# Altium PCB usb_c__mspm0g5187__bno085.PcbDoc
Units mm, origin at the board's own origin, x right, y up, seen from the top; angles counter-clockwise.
Board outline 92 x 60 mm, 2 copper layers (Top, Bottom), stack 0 mm thick; 42 components, 34 nets, 214 pads, 80 vias.
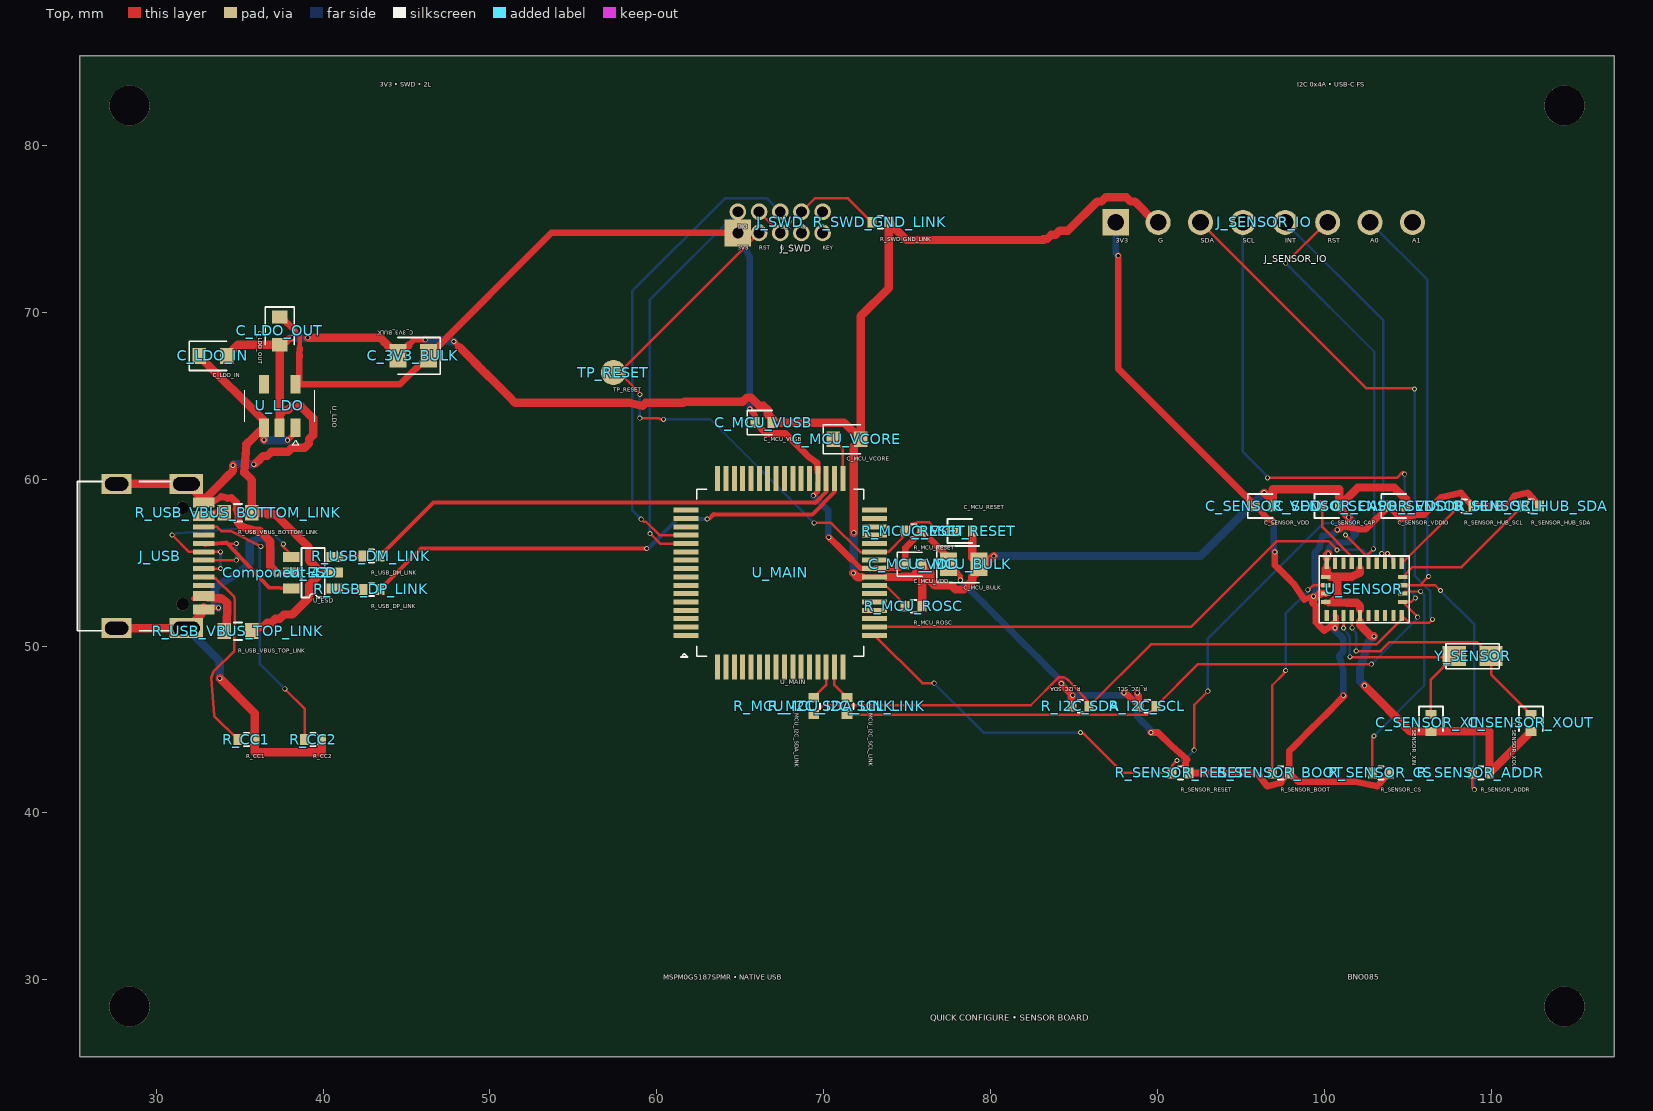
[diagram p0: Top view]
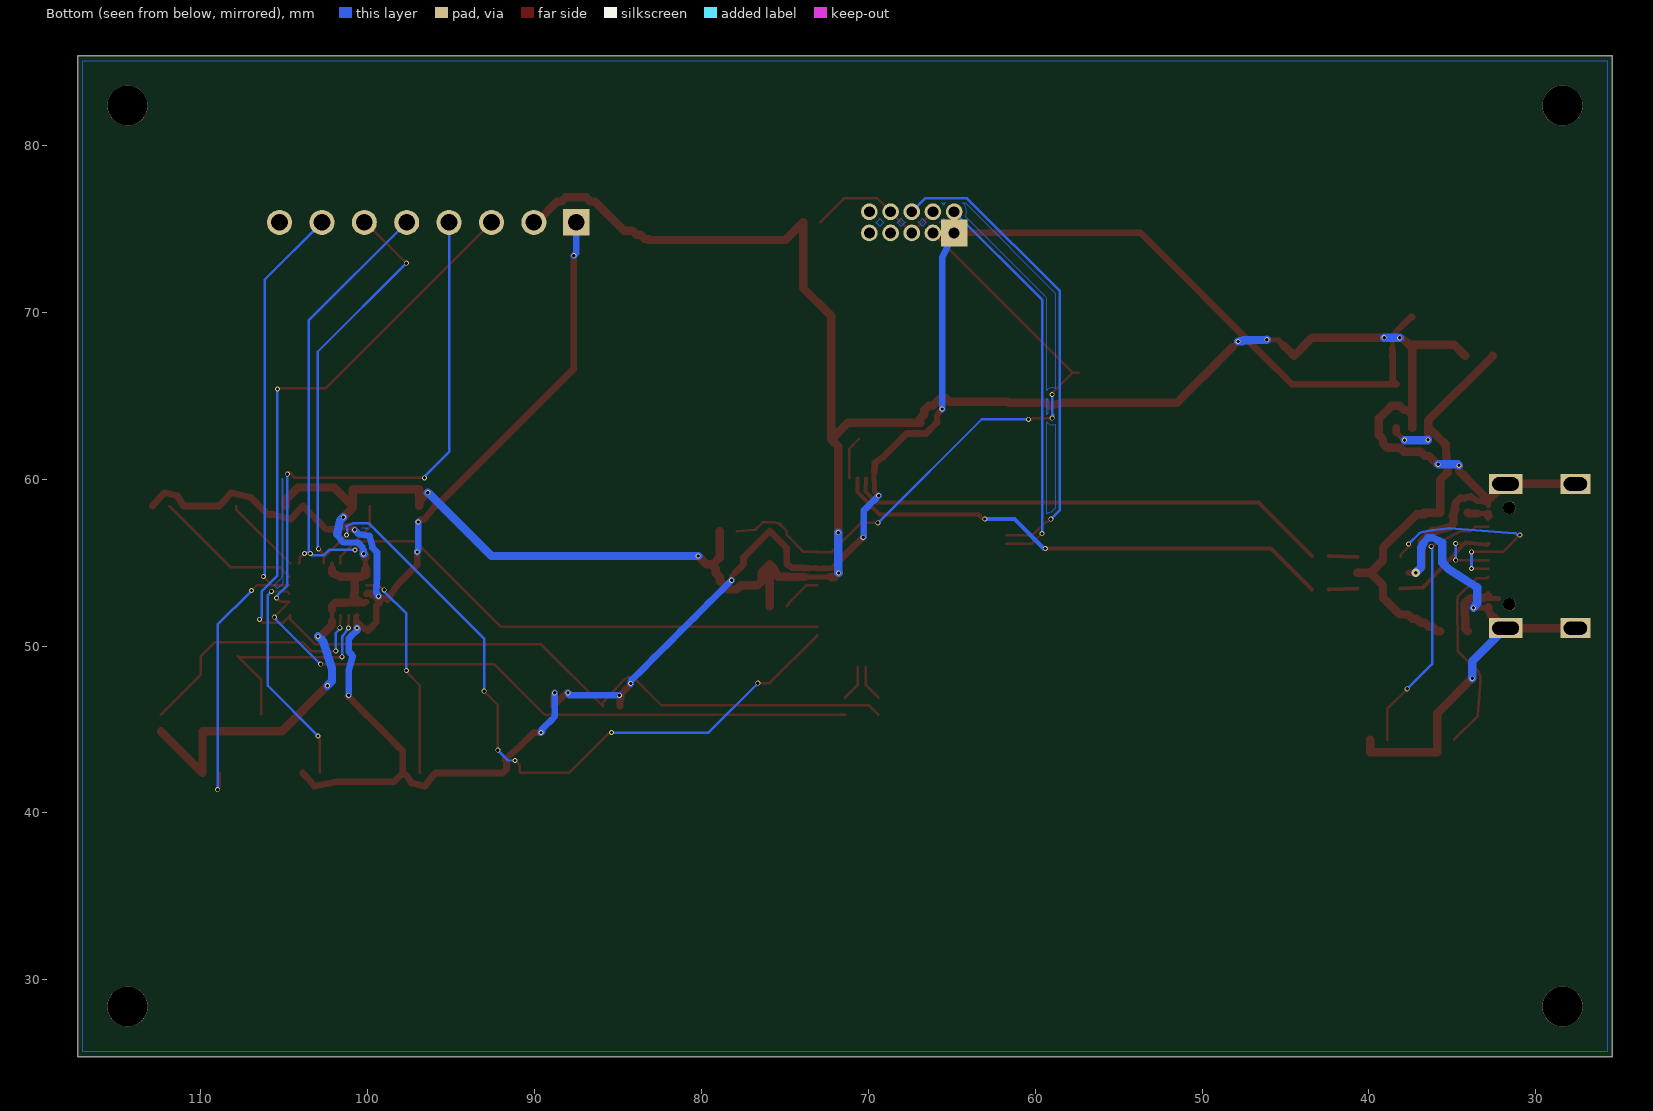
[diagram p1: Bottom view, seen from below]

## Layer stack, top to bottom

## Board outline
25.4,85.4 117.4,85.4 117.4,25.4 25.4,25.4

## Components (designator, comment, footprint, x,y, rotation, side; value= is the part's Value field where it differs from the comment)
C_3V3_BULK "" TSCIRCUIT-2.8500x1.4000mm 45.4,67.4 r180 top
C_LDO_IN "" TSCIRCUIT-2.4500x0.9500mm 33.4,67.4 r0 top
C_LDO_OUT "" TSCIRCUIT-0.9500x2.4500mm 37.4,68.9 r270 top
C_MCU_BULK "" TSCIRCUIT-2.8500x1.4000mm 78.4,54.9 r0 top
C_MCU_RESET "" TSCIRCUIT-1.5600x0.6400mm 78.4,56.9 r0 top
C_MCU_VCORE "" TSCIRCUIT-2.4500x0.9500mm 71.4,62.4 r0 top
C_MCU_VDD "" TSCIRCUIT-1.5600x0.6400mm 75.4,54.9 r0 top
C_MCU_VUSB "" TSCIRCUIT-1.5600x0.6400mm 66.4,63.4 r0 top
C_SENSOR_CAP "" TSCIRCUIT-1.5600x0.6400mm 100.4,58.4 r0 top
C_SENSOR_VDD "" TSCIRCUIT-1.5600x0.6400mm 96.4,58.4 r0 top
C_SENSOR_VDDIO "" TSCIRCUIT-1.5600x0.6400mm 104.4,58.4 r0 top
C_SENSOR_XIN "" TSCIRCUIT-0.6400x1.5600mm 106.4,45.4 r270 top
C_SENSOR_XOUT "" TSCIRCUIT-0.6400x1.5600mm 112.4,45.4 r270 top
Component-42 "" TSCIRCUIT-0.5000x0.5000mm 37.2,54.4 r0 top
J_SENSOR_IO "" TSCIRCUIT-19.2800x1.5000mm 96.4,75.4 r0 top
J_SWD "" TSCIRCUIT-6.0800x2.2700mm 67.4,75.4 r0 top
J_USB "" TSCIRCUIT-6.7732x9.8502mm 30.113,55.4 r90 top
R_CC1 "" TSCIRCUIT-1.5600x0.6400mm 35.4,44.4 r0 top
R_CC2 "" TSCIRCUIT-1.5600x0.6400mm 39.4,44.4 r0 top
R_I2C_SCL "" TSCIRCUIT-1.5600x0.6400mm 89.4,46.4 r180 top
R_I2C_SDA "" TSCIRCUIT-1.5600x0.6400mm 85.4,46.4 r180 top
R_MCU_I2C_SCL_LINK "" TSCIRCUIT-0.6400x1.5600mm 71.4,46.4 r270 top
R_MCU_I2C_SDA_LINK "" TSCIRCUIT-0.6400x1.5600mm 69.4,46.4 r270 top
R_MCU_RESET "" TSCIRCUIT-1.5600x0.6400mm 75.4,56.9 r0 top
R_MCU_ROSC "" TSCIRCUIT-1.5600x0.6400mm 75.4,52.4 r0 top
R_SENSOR_ADDR "" TSCIRCUIT-1.5600x0.6400mm 109.4,42.4 r0 top
R_SENSOR_BOOT "" TSCIRCUIT-1.5600x0.6400mm 97.4,42.4 r0 top
R_SENSOR_CS "" TSCIRCUIT-1.5600x0.6400mm 103.4,42.4 r0 top
R_SENSOR_HUB_SCL "" TSCIRCUIT-1.5600x0.6400mm 108.4,58.4 r0 top
R_SENSOR_HUB_SDA "" TSCIRCUIT-1.5600x0.6400mm 112.4,58.4 r0 top
R_SENSOR_RESET "" TSCIRCUIT-1.5600x0.6400mm 91.4,42.4 r0 top
R_SWD_GND_LINK "" TSCIRCUIT-1.5600x0.6400mm 73.4,75.4 r0 top
R_USB_DM_LINK "" TSCIRCUIT-1.5600x0.6400mm 42.9,55.4 r0 top
R_USB_DP_LINK "" TSCIRCUIT-1.5600x0.6400mm 42.9,53.4 r0 top
R_USB_VBUS_BOTTOM_LINK "" TSCIRCUIT-2.4500x0.9500mm 34.9,58 r0 top
R_USB_VBUS_TOP_LINK "" TSCIRCUIT-2.4500x0.9500mm 34.9,50.9 r0 top
TP_RESET "" TSCIRCUIT-1.5000x1.5000mm 57.4,66.4 r0 top
U_ESD "" TSCIRCUIT-3.6000x2.5000mm 39.4,54.4 r0 top
U_LDO "" TSCIRCUIT-2.5000x3.7000mm 37.4,64.4 r270 top
U_MAIN "" TSCIRCUIT-12.8000x12.8000mm 67.4,54.4 r0 top
U_SENSOR "" TSCIRCUIT-5.2000x3.8000mm 102.4,53.4 r0 top
Y_SENSOR "" TSCIRCUIT-3.6000x1.2000mm 108.9,49.4 r0 top

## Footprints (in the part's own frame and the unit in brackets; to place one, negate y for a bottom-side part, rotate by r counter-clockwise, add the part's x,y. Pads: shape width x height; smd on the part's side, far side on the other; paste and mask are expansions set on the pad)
TSCIRCUIT-0.5000x0.5000mm [mm]
TSCIRCUIT-0.6400x1.5600mm [mm]
  rect 0.54x0.64 smd: 1(-0.51,0) 2(0.51,0)
  silkscreen extent -0.98,-0.72 0.51,0.72
TSCIRCUIT-0.9500x2.4500mm [mm]
  rect 0.8x0.95 smd: 1(-0.825,0) 2(0.825,0)
  silkscreen extent -1.43,-0.87 0.82,0.88
TSCIRCUIT-1.5000x1.5000mm [mm]
  round 1.5 smd: 1(0,0)
TSCIRCUIT-1.5600x0.6400mm [mm]
  rect 0.54x0.64 smd: 1(-0.51,0) 2(0.51,0)
  silkscreen extent -0.98,-0.72 0.51,0.72
TSCIRCUIT-2.4500x0.9500mm [mm]
  rect 0.8x0.95 smd: 1(-0.825,0) 2(0.825,0)
  silkscreen extent -1.42,-0.87 0.82,0.87
TSCIRCUIT-2.5000x3.7000mm [mm]
  rect 1.1x0.6 smd: 1(1.3,0.95) 2(1.3,0) 3(1.3,-0.95) 4(-1.3,-0.95) 5(-1.3,0.95)
  silkscreen extent -0.95,-2.1 2.35,2.1
TSCIRCUIT-2.8500x1.4000mm [mm]
  rect 1.025x1.4 smd: 1(-0.913,0) 2(0.913,0)
  silkscreen extent -1.63,-1.1 0.91,1.1
TSCIRCUIT-3.6000x1.2000mm [mm]
  rect 1.4x1.2 smd: 1(-1.1,0) 2(1.1,0)
  silkscreen extent -1.6,-0.75 1.6,0.75
TSCIRCUIT-3.6000x2.5000mm [mm]
  rect 1x0.6 smd: 1(-1.3,-0.95) 2(-1.3,0) 3(-1.3,0.95) 4(1.3,0.95) 5(1.3,0) 6(1.3,-0.95)
  silkscreen extent -0.7,-1.49 0.7,1.49
TSCIRCUIT-5.2000x3.8000mm [mm]
  rect 0.25x0.675 smd: 1(-2.25,-1.562) 6(-2.25,1.563) 7(-1.75,1.563) 8(-1.25,1.563) 9(-0.75,1.563) 10(-0.25,1.563) 11(0.25,1.563) 12(0.75,1.563) 13(1.25,1.563) 14(1.75,1.563) 15(2.25,1.563) 20(2.25,-1.562) 21(1.75,-1.562) 22(1.25,-1.562) 23(0.75,-1.562) 24(0.25,-1.562) 25(-0.25,-1.562) 26(-0.75,-1.562) 27(-1.25,-1.562) 28(-1.75,-1.562)
  rect 0.575x0.25 smd: 2(-2.312,-0.75) 3(-2.312,-0.25) 4(-2.312,0.25) 5(-2.312,0.75) 16(2.312,0.75) 17(2.312,0.25) 18(2.312,-0.25) 19(2.312,-0.75)
  silkscreen extent -2.7,-2 2.7,2
TSCIRCUIT-6.0800x2.2700mm [mm]
  rect 1.6x1.6 hole 0.65: 1(-2.54,-0.635)
  round 1 hole 0.65: 2(-2.54,0.635) 3(-1.27,0.635) 4(0,0.635) 5(1.27,0.635) 6(2.54,0.635) 7(2.54,-0.635) 8(1.27,-0.635) 9(0,-0.635) 10(-1.27,-0.635)
TSCIRCUIT-6.7732x9.8502mm [mm]
  rect 0.3x1.3 smd: 1(-3.35,-2.737) 2(-3.05,-2.737) 3(-2.55,-2.737) 4(-2.25,-2.737) 5(-1.75,-2.737) 6(-1.25,-2.737) 7(-0.75,-2.737) 8(-0.25,-2.737) 9(0.25,-2.737) 10(0.75,-2.737) 11(1.25,-2.737) 12(1.75,-2.737) 13(2.55,-2.737) 14(2.25,-2.737) 15(3.35,-2.737) 16(3.05,-2.737)
  rect 1.2x2 hole 0.8 slot 1.6 at 90 deg: 17(-4.325,-1.693) 18(4.325,-1.693)
  rect 1.2x1.8 hole 0.8 slot 1.4 at 90 deg: 19(4.325,2.487) 20(-4.325,2.487)
  round 0.75 hole 0.75 unplated: NPTH-1(-2.9,-1.468) NPTH-2(2.9,-1.468)
  silkscreen extent -4.47,-0.75 4.47,4.83
TSCIRCUIT-12.8000x12.8000mm [mm]
  rect 1.5x0.3 smd: 1(-5.65,-3.75) 2(-5.65,-3.25) 3(-5.65,-2.75) 4(-5.65,-2.25) 5(-5.65,-1.75) 6(-5.65,-1.25) 7(-5.65,-0.75) 8(-5.65,-0.25) 9(-5.65,0.25) 10(-5.65,0.75) 11(-5.65,1.25) 12(-5.65,1.75) 13(-5.65,2.25) 14(-5.65,2.75) 15(-5.65,3.25) 16(-5.65,3.75) 33(5.65,3.75) 34(5.65,3.25) 35(5.65,2.75) 36(5.65,2.25) 37(5.65,1.75) 38(5.65,1.25) 39(5.65,0.75) 40(5.65,0.25) 41(5.65,-0.25) 42(5.65,-0.75) 43(5.65,-1.25) 44(5.65,-1.75) 45(5.65,-2.25) 46(5.65,-2.75) 47(5.65,-3.25) 48(5.65,-3.75)
  rect 0.3x1.5 smd: 17(-3.75,5.65) 18(-3.25,5.65) 19(-2.75,5.65) 20(-2.25,5.65) 21(-1.75,5.65) 22(-1.25,5.65) 23(-0.75,5.65) 24(-0.25,5.65) 25(0.25,5.65) 26(0.75,5.65) 27(1.25,5.65) 28(1.75,5.65) 29(2.25,5.65) 30(2.75,5.65) 31(3.25,5.65) 32(3.75,5.65) 49(3.75,-5.65) 50(3.25,-5.65) 51(2.75,-5.65) 52(2.25,-5.65) 53(1.75,-5.65) 54(1.25,-5.65) 55(0.75,-5.65) 56(0.25,-5.65) 57(-0.25,-5.65) 58(-0.75,-5.65) 59(-1.25,-5.65) 60(-1.75,-5.65) 61(-2.25,-5.65) 62(-2.75,-5.65) 63(-3.25,-5.65) 64(-3.75,-5.65)
  silkscreen extent -5.95,-5.05 5,5
TSCIRCUIT-19.2800x1.5000mm [mm]
  rect 1.6x1.6 hole 1: 1(-8.89,0)
  round 1.5 hole 1: 2(-6.35,0) 3(-3.81,0) 4(-1.27,0) 5(1.27,0) 6(3.81,0) 7(6.35,0) 8(8.89,0)

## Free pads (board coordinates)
  round 2.4 hole 2.4 unplated: NPTH-3(28.4,28.4) NPTH-4(114.4,28.4) NPTH-5(28.4,82.4) NPTH-6(114.4,82.4)

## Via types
v1: diameter 0.3, hole 0.2, Top to Bottom, 79 vias
v2: diameter 0.5, hole 0.2, Top to Bottom, 1 vias

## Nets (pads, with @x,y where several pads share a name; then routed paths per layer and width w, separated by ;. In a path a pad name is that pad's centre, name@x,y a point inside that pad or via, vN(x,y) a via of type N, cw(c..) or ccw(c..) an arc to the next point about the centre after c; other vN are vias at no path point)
".J_SWD > .pin2 to .U_MAIN > .pin12": J_SWD.2 U_MAIN.12 | length 23.9
  Top w0.15: v1(59.59,56.74) 59.688,56.646 59.705,56.646 60.201,56.15 U_MAIN.12
  Bottom w0.15: v1(59.59,56.74) 59.592,70.767 J_SWD.2
".J_SWD > .pin4 to .U_MAIN > .pin13": J_SWD.4 U_MAIN.13 | length 28.5
  Top w0.15: v1(59.06,57.616) 59.207,57.469 59.34,57.47 60.16,56.651 U_MAIN.13
  Bottom w0.15: v1(59.06,57.616) 58.521,58.155 58.521,71.279 64.083,76.841 66.594,76.841 J_SWD.4
".U_MAIN > .pin42 to .R_MCU_ROSC > .pin1": R_MCU_ROSC.1 U_MAIN.42 | length 2.4
  Top w0.15: U_MAIN.42 73.719,53.65 74.769,52.6 74.769,52.521 R_MCU_ROSC.1
".U_SENSOR > .CAP to .C_SENSOR_CAP > .pin1": C_SENSOR_CAP.1 U_SENSOR.9 | length 4.2
  Top w0.15: C_SENSOR_CAP.1 99.891,57.135 101.647,55.379 101.646,54.966 U_SENSOR.9
".U_SENSOR > .SENSOR_HUB_SCL to .R_SENSOR_HUB_SCL > .pin1": R_SENSOR_HUB_SCL.1 U_SENSOR.15 | length 4.8
  Top w0.15: U_SENSOR.15 107.89,58.202 R_SENSOR_HUB_SCL.1
".U_SENSOR > .SENSOR_HUB_SDA to .R_SENSOR_HUB_SDA > .pin1": R_SENSOR_HUB_SDA.1 U_SENSOR.16 | length 8.9
  Top w0.15: U_SENSOR.16 105.305,54.742 105.468,54.742 108.232,54.742 R_SENSOR_HUB_SDA.1
GND: C_3V3_BULK.2 C_LDO_IN.2 C_LDO_OUT.2 C_MCU_BULK.2 C_MCU_RESET.2 C_MCU_VCORE.2 C_MCU_VDD.2 C_MCU_VUSB.2 C_SENSOR_CAP.2 C_SENSOR_VDD.2 C_SENSOR_VDDIO.2 C_SENSOR_XIN.2 C_SENSOR_XOUT.2 J_SENSOR_IO.2 J_USB.1 J_USB.2 J_USB.15 J_USB.16 J_USB.17 J_USB.18 J_USB.19 J_USB.20 R_CC1.2 R_CC2.2 R_MCU_ROSC.2 R_SENSOR_ADDR.2 R_SWD_GND_LINK.2 U_ESD.2 U_LDO.2 U_MAIN.41 U_SENSOR.2 U_SENSOR.5 U_SENSOR.6 U_SENSOR.10 U_SENSOR.25 | length 223.9
  Top w0.25: U_SENSOR.2 U_SENSOR.2@100.375,52.639 ; U_SENSOR.5@100.088,54.275 U_SENSOR.5 U_SENSOR.5@100.375,54.15 ; U_SENSOR.6@100.088,54.625 100.088,54.9 U_SENSOR.6 ; U_SENSOR.6@100.15,54.625 U_SENSOR.6 ; U_SENSOR.6@100.15,55.3 U_SENSOR.6 ; 102.15,51.5 U_SENSOR.25 U_SENSOR.25@102.15,52.175 ; U_SENSOR.10@102.15,54.625 U_SENSOR.10
  Top w0.275: J_USB.16 J_USB.15@33.056,58.661
  Top w0.3: J_USB.1@32.699,51.9 J_USB.1 J_USB.1@32.849,52.2 ; J_USB.15@32.699,58.9 J_USB.15 ; J_USB.2 J_USB.2@32.899,52.3 ; J_USB.16@32.849,58.6 J_USB.15 ; J_USB.15@32.999,58.9 J_USB.15 ; 72.3,54.15 U_MAIN.41 73.144,54.15 73.237,54.15 73.331,54.15 73.425,54.15 73.519,54.15 73.612,54.15 73.706,54.15 U_MAIN.41@73.8,54.15
  Top w0.312: 45.418,68.331 45.675,68.35 45.931,68.369 v1(46.119,68.365)
  Top w0.325: J_USB.16 J_USB.16@32.849,58.6 ; J_USB.2@32.899,52.3 v1(33.731,52.3) ; v1(47.832,68.263) 48.166,67.929
  Top w0.35: v1(35.851,60.894) v1@35.859,60.947 ; 37.968,68.441 38.124,68.441 v1(38.153,68.477) ; 45.108,68.02 45.418,68.331
  Top w0.375: J_USB.15@33.056,58.661 33.504,58.707 33.9,58.963 ; v1@35.859,60.947 v1@35.959,60.947 ; U_SENSOR.2 U_SENSOR.2@100.275,52.587 ; U_SENSOR.2@100.375,52.639 100.509,52.634
  Top w0.4: 37.2,54.4 U_ESD.2@37.6,54.4 ; 72.175,54.12 72.205,54.15 ; U_SENSOR.2@100.275,52.587 100.556,52.775 100.837,52.963
  Top w0.425: C_LDO_OUT.2@37.785,68.258 37.968,68.441
  Top w0.437: 33.9,58.963 34.275,58.869 34.504,58.9 34.796,58.608
  Top w0.45: 72.205,54.15 72.3,54.15
  Top w0.475: 34.796,58.608 34.837,58.4 34.833,58.2 ; U_MAIN.41@73.8,54.15 74.253,54.15 74.707,54.15
  Top w0.5: J_USB.20 J_USB.17 31.874,51.075 32.474,51.675 32.699,51.9 ; J_USB.19 J_USB.18 31.874,59.725 32.474,59.125 32.699,58.9 ; J_USB.1@32.849,52.2 J_USB.2 ; 32.999,58.9 33.2,59.101 33.551,59.452 33.901,59.802 34.252,60.153 34.603,60.504 v1(34.603,60.841) ; v1(33.81,48.076) 35.91,45.976 R_CC1.2 35.91,43.65 39.91,43.65 R_CC2.2 ; C_LDO_IN.2 34.9,68.075 C_LDO_OUT.2 ; 34.833,58.2 34.967,57.8 34.9,57.4 35.15,57.15 35.923,56.926 36.186,56.926 36.838,56.275 36.838,54.762 37.2,54.4 ; v1@35.959,60.947 36.248,61.235 36.163,61.15 36.15,61.15 36.4,61.4 36.65,61.4 36.9,61.65 37.9,61.65 38.15,61.9 38.9,61.9 39.15,62.15 39.15,62.4 39.4,62.65 39.4,63.65 38.65,64.4 38.15,64.4 37.9,64.15 37.65,64.15 37.4,63.9 U_LDO.2 C_LDO_OUT.2 ; C_LDO_OUT.2@37.785,68.258 37.603,68.075 C_LDO_OUT.2 ; v1(39.081,68.491) 39.56,68.491 40.04,68.491 40.519,68.491 40.999,68.491 41.478,68.491 41.958,68.491 42.437,68.491 42.917,68.491 43.396,68.491 43.669,68.218 43.942,67.946 44.215,67.673 C_3V3_BULK.2 44.798,67.71 45.108,68.02 ; 48.166,67.929 48.5,67.595 48.834,67.261 49.169,66.926 49.503,66.592 49.837,66.258 50.171,65.924 50.505,65.59 50.84,65.255 51.174,64.921 51.508,64.587 51.997,64.587 52.485,64.587 52.973,64.587 53.462,64.587 53.95,64.587 54.439,64.587 54.927,64.587 55.415,64.587 55.904,64.587 56.392,64.587 56.881,64.587 57.369,64.587 57.857,64.587 58.346,64.587 59.15,64.4 59.323,64.587 59.811,64.587 60.3,64.587 60.788,64.587 61.276,64.587 61.587,64.587 61.65,64.65 65.15,64.65 65.4,64.9 65.65,64.9 66.15,64.4 66.4,64.4 66.65,64.15 66.65,63.9 66.9,63.65 66.9,63.4 C_MCU_VUSB.2 71.225,63.4 C_MCU_VCORE.2 ; v1(71.783,54.383) 72.043,54.113 72.175,54.12 ; 74.707,54.15 75.4,54.15 75.66,54.65 C_MCU_VDD.2 ; R_MCU_ROSC.2 C_MCU_VDD.2 ; C_MCU_RESET.2 78.91,55.303 C_MCU_BULK.2 ; v1(80.2,55.4) 80.137,55.337 80.132,55.337 79.913,55.118 79.695,54.9 C_MCU_BULK.2 ; J_SENSOR_IO.2 89.9,75.4 88.65,76.65 88.4,76.65 88.15,76.9 86.9,76.9 86.65,76.65 86.4,76.65 84.65,74.9 84.15,74.9 83.9,74.65 83.65,74.65 83.4,74.4 83.15,74.4 83.15,74.394 83.199,74.345 82.716,74.345 82.233,74.345 81.75,74.345 81.267,74.345 80.784,74.345 80.301,74.345 79.818,74.345 79.335,74.345 78.851,74.345 78.368,74.345 77.885,74.345 77.402,74.345 76.919,74.345 76.436,74.345 75.953,74.345 75.47,74.345 74.987,74.345 74.965,74.345 74.613,74.697 74.262,75.048 R_SWD_GND_LINK.2 73.91,71.464 72.225,69.779 72.225,69.287 72.225,68.795 72.225,68.303 72.225,67.812 72.225,67.32 72.225,66.828 72.225,66.336 72.225,65.844 72.225,65.352 72.225,64.86 72.225,64.368 72.225,63.876 72.225,63.384 72.225,62.892 C_MCU_VCORE.2 ; v1(96.4,59.2) 96.91,58.69 C_SENSOR_VDD.2 96.91,59.4 100.91,59.4 C_SENSOR_CAP.2 ; 100.088,54.275 100.088,54.625 ; 100.15,54.625 100.15,54.4 100.4,54.15 101.65,54.15 102.15,54.4 102.15,54.625 ; U_SENSOR.6@100.15,55.3 100.15,55.436 v1(100.249,55.535) ; U_SENSOR.5@100.375,54.15 100.775,54.15 100.775,53.338 100.837,52.963 ; 100.509,52.634 100.931,52.619 101.353,52.603 101.947,52.603 102.15,52.4 U_SENSOR.25@102.15,52.175 ; v1(101.469,57.73) 100.91,58.289 C_SENSOR_CAP.2 ; 102.15,51.5 102.15,51.275 102.275,51.15 102.834,50.591 v1(102.986,50.591) ; v1(102.417,47.634) 105.161,44.89 C_SENSOR_XIN.2 109.91,44.89 R_SENSOR_ADDR.2 110.087,42.577 C_SENSOR_XOUT.2 ; C_SENSOR_VDDIO.2 104.91,58.802 104.199,59.513 102.023,59.513 C_SENSOR_CAP.2 ; v1(71.813,56.799) v1(71.813,56.799) ; v1(71.813,56.799) 71.814,56.82 71.814,61.989 C_MCU_VCORE.2 ; C_MCU_VDD.2 75.91,54.89 76.4,54.4 76.4,53.9 76.65,53.65 77.65,53.65 77.9,53.4 78.4,53.4 78.9,53.9 78.9,54.15 79.15,54.4 79.15,54.65 79.4,54.9 C_MCU_BULK.2
  Bottom w0.375: 100.261,55.75 100.338,55.962 100.588,56.213 101.025,56.213 101.462,56.213 101.588,56.337 101.838,56.713
  Bottom w0.437: 36.181,56.494 36.473,56.494 36.748,56.143
  Bottom w0.45: 35.828,56.316 36.181,56.494 ; v1@100.261,55.548 100.261,55.75
  Bottom w0.475: 35.6,56.2 35.828,56.316
  Bottom w0.5: J_USB.17 33.81,49.071 v1(33.81,48.076) ; v1(33.731,52.3) 33.514,52.565 33.513,53.044 33.512,53.523 35.2,54.6 35.6,55 35.6,55.4 35.6,55.8 35.6,56.2 ; v1(34.603,60.841) 34.656,60.894 34.795,60.894 35.147,60.894 35.499,60.894 v1(35.851,60.894) ; 36.748,56.143 36.878,55.855 36.878,54.722 37.2,54.4 ; v1(38.153,68.477) 39.067,68.477 v1(39.081,68.491) ; v1(46.119,68.365) 46.593,68.354 47.067,68.344 47.541,68.333 47.595,68.278 47.771,68.278 v1(47.832,68.263) ; v1(71.783,54.383) 71.813,54.413 v1(71.813,56.799) ; v1(80.2,55.4) 80.683,55.4 81.166,55.4 81.649,55.4 82.132,55.4 82.615,55.4 83.099,55.4 83.582,55.4 84.065,55.4 84.548,55.4 85.031,55.4 85.514,55.4 85.997,55.4 86.48,55.4 86.963,55.4 87.446,55.4 87.93,55.4 88.413,55.4 92.6,55.4 v1(96.4,59.2) ; v1(100.249,55.535) v1@100.261,55.548 ; v1(101.469,57.73) 101.666,57.533 101.752,57.123 101.838,56.713 ; v1(102.417,47.634) 102.15,47.901 102.15,48.65 102.694,50.302 102.983,50.591 v1(102.986,50.591)
MAIN_RESET: C_MCU_RESET.1 J_SWD.10 R_MCU_RESET.1 TP_RESET.1 U_MAIN.38 | length 39.3
  Top w0.15: v1(58.981,63.66) 60.154,63.66 60.207,63.607 60.394,63.607 v1(60.402,63.599) ; v1(58.982,65.085) 59.023,65.126 57.75,66.4 TP_RESET.1 57.765,66.4 J_SWD.10 ; v1(69.428,57.392) 70.448,57.392 72.198,55.642 73.042,55.642 U_MAIN.38 73.889,55.65 74.889,56.651 R_MCU_RESET.1@74.889,56.899 ; R_MCU_RESET.1 75.256,57.266 75.34,57.266 75.256,57.35 75.65,57.423 75.9,57.425 76.15,57.425 76.323,57.425 76.764,56.984 C_MCU_RESET.1
  Bottom w0.15: v1(58.981,63.66) 58.931,63.71 58.931,63.858 58.982,63.909 v1(58.982,65.085) ; v1(60.402,63.599) 63.204,63.599 69.352,57.451 69.369,57.451 v1(69.428,57.392)
MCU_I2C_SCL_LOCAL: R_MCU_I2C_SCL_LINK.1 U_MAIN.50 | length 2.2
  Top w0.15: U_MAIN.50 70.65,47.66 R_MCU_I2C_SCL_LINK.1
MCU_I2C_SDA_LOCAL: R_MCU_I2C_SDA_LINK.1 U_MAIN.51 | length 2.2
  Top w0.15: R_MCU_I2C_SDA_LINK.1 70.15,47.66 U_MAIN.51
MSPM0_VCORE: C_MCU_VCORE.1 U_MAIN.32 | length 2.6
  Top w0.15: C_MCU_VCORE.1 71.15,61.825 U_MAIN.32
SENSOR_ADDR0: J_SENSOR_IO.7 R_SENSOR_ADDR.1 U_SENSOR.17 | length 40.7
  Top w0.15: v1(106.259,54.177) 105.732,53.65 U_SENSOR.17 106.657,53.65 v1(106.971,53.336) ; R_SENSOR_ADDR.1 108.89,41.517 108.973,41.434 108.973,41.427 v1(109,41.4)
  Bottom w0.15: J_SENSOR_IO.7 106.19,71.96 106.19,54.325 106.19,54.246 v1(106.259,54.177) ; v1(106.971,53.336) 107.034,53.273 107.034,53.255 109,51.289 v1(109,41.4)
SENSOR_ADDR1: J_SENSOR_IO.8
SENSOR_BOOT: R_SENSOR_BOOT.1 U_SENSOR.4 | length 13
  Top w0.15: R_SENSOR_BOOT.1 96.89,47.658 97.592,48.359 97.592,48.44 v1(97.695,48.543) ; v1(99.026,53.38) 99.335,53.65 U_SENSOR.4
  Bottom w0.15: v1(97.695,48.543) 97.695,51.954 99.027,53.285 99.027,53.341 v1(99.026,53.38)
SENSOR_CS: R_SENSOR_CS.1 U_SENSOR.18 | length 13.4
  Top w0.15: R_SENSOR_CS.1 102.89,44.524 102.979,44.613 v1(102.983,44.617) ; U_SENSOR.18 104.836,53.273 v1(105.787,53.284)
  Bottom w0.15: v1(102.983,44.617) 105.991,47.625 105.991,52.984 105.991,53.06 105.87,53.181 v1(105.787,53.284)
SENSOR_INT: J_SENSOR_IO.5 U_MAIN.47 U_SENSOR.14 | length 57.2
  Top w0.15: U_MAIN.47 92.017,51.15 97.167,56.3 100.25,56.3 100.698,55.852 v1(100.773,55.765) ; v1(103.446,55.55) 103.851,55.55 104.088,55.313 104.088,55.024 U_SENSOR.14 104.081,55.031 104.081,55.276 103.806,55.55 v1(103.8,55.55)
  Bottom w0.15: J_SENSOR_IO.5 103.554,69.516 103.554,55.658 v1(103.8,55.55) ; v1(100.773,55.765) 102.318,55.775 102.639,55.454 103.35,55.454 103.376,55.481 v1(103.446,55.55)
SENSOR_RESET: J_SENSOR_IO.6 R_SENSOR_RESET.1 U_MAIN.48 U_SENSOR.11 | length 68.3
  Top w0.15: U_MAIN.48 75.92,47.78 v1(76.624,47.78) ; v1(85.4,44.82) 85.485,44.735 85.607,44.735 87.942,42.4 R_SENSOR_RESET.1 90.89,42.856 91.092,43.058 v1(91.176,43.142) ; v1(92.213,43.762) 92.213,46.478 92.943,47.208 92.943,47.213 v1(93.031,47.301) ; v1(97.688,72.957) 97.712,72.981 100.131,75.4 J_SENSOR_IO.6 ; v1(101.276,56.665) 102.65,55.291 U_SENSOR.11 102.65,55.53 v1(102.952,55.832)
  Bottom w0.15: v1(76.624,47.78) 76.627,47.777 79.584,44.82 v1(85.4,44.82) ; v1(91.176,43.142) 91.617,43.166 92.204,43.753 v1(92.213,43.762) ; v1(93.031,47.301) 93.031,50.456 99.937,57.362 100.886,57.362 101.281,57.193 101.228,57.021 101.228,56.802 101.248,56.782 101.248,56.693 v1(101.276,56.665) ; v1(97.688,72.957) 103,67.645 103,55.909 103,55.88 v1(102.952,55.832)
SENSOR_SCL: J_SENSOR_IO.4 R_I2C_SCL.1 R_MCU_I2C_SCL_LINK.2 U_SENSOR.19 | length 70.8
  Top w0.15: R_MCU_I2C_SCL_LINK.2 89.4,45.89 R_I2C_SCL.1 92.421,48.911 102.62,48.911 102.811,48.911 v1(102.829,48.917) ; v1(96.602,60.084) 104.359,60.084 104.706,60.431 104.708,60.431 v1(104.826,60.313) ; v1(105.461,52.887) 105.222,52.65 U_SENSOR.19 105.609,51.754 v1(105.609,51.738)
  Bottom w0.15: J_SENSOR_IO.4 95.13,61.642 96.538,60.234 96.538,60.148 v1(96.602,60.084) ; v1(102.829,48.917) 105.489,51.576 105.489,51.618 v1(105.609,51.738) ; v1(104.826,60.313) 104.826,53.631 105.402,53.054 105.402,52.966 v1(105.461,52.887)
SENSOR_SDA: J_SENSOR_IO.3 R_I2C_SDA.1 R_MCU_I2C_SDA_LINK.2 U_SENSOR.20 | length 72.8
  Top w0.15: R_MCU_I2C_SDA_LINK.2 69.971,46.448 82.413,46.459 84.099,48.146 84.382,48.149 84.674,47.958 85.913,46.619 R_I2C_SDA.1 89.612,50.102 103.128,50.1 104.662,51.615 U_SENSOR.20 105.079,51.408 105.079,51.396 106.283,51.396 v1(106.49,51.603) ; J_SENSOR_IO.3 102.519,65.471 105.342,65.471 105.362,65.471 v1(105.417,65.416)
  Bottom w0.15: v1(105.417,65.416) 105.417,54.234 106.347,53.304 106.347,51.746 v1(106.49,51.603)
SENSOR_XIN: C_SENSOR_XIN.1 U_SENSOR.27 Y_SENSOR.1 | length 13
  Top w0.15: U_SENSOR.27 U_SENSOR.27 v1(101.16,51.085) ; v1(101.544,49.355) 101.551,49.324 101.582,49.324 107.724,49.324 Y_SENSOR.1 106.4,48 C_SENSOR_XIN.1
  Bottom w0.15: v1(101.16,51.085) 101.153,51.085 101.52,50.583 v1(101.544,49.355)
SENSOR_XOUT: C_SENSOR_XOUT.1 U_SENSOR.26 Y_SENSOR.2 | length 15.4
  Top w0.15: U_SENSOR.26 101.613,51.8 v1(101.675,51.1) ; v1(101.921,49.712) 101.926,49.707 102.138,49.707 103.38,49.707 103.915,50.241 109.159,50.241 Y_SENSOR.2 110,48.31 C_SENSOR_XOUT.1
  Bottom w0.15: v1(101.675,51.1) 101.621,51.09 101.621,51.084 101.921,50.785 v1(101.921,49.712)
swd-ground-1-to-2: J_SWD.3 J_SWD.5 J_SWD.9 R_SWD_GND_LINK.1 | length 8.8
  Top w0.15: J_SWD.3 J_SWD.9 J_SWD.5 69.481,76.846 71.471,76.846 71.471,76.819 R_SWD_GND_LINK.1
usb-dm-device: R_USB_DM_LINK.1 U_ESD.4 | length 1.7
  Top w0.25: U_ESD.4 R_USB_DM_LINK.1
usb-dm-mcu: R_USB_DM_LINK.2 U_MAIN.30 | length 29.2
  Top w0.25: R_USB_DM_LINK.2 46.621,58.611 69.501,58.593 70.166,59.262 U_MAIN.30
usb-dm-port-tie: J_USB.7 J_USB.9 U_ESD.3 | length 13.4
  Top w0.15: v1(30.956,56.662) 31.968,55.65 J_USB.9 v1(33.85,55.65) ; J_USB.7 v1(33.85,54.65) ; v1(37.617,56.127) 37.533,56.043 38.1,55.477 U_ESD.3
  Bottom w0.15: v1(30.956,56.662) 31.091,56.662 31.197,56.768 31.296,56.768 35.189,57.075 36.209,56.953 36.72,56.871 36.976,56.769 v1(37.617,56.127) ; v1(33.85,54.65) v1(33.85,55.65)
usb-dp-device: R_USB_DP_LINK.1 U_ESD.6 | length 1.7
  Top w0.25: U_ESD.6 R_USB_DP_LINK.1
usb-dp-mcu: R_USB_DP_LINK.2 U_MAIN.31 | length 30.5
  Top w0.25: R_USB_DP_LINK.2 45.859,55.849 v1(59.393,55.849) ; v1(63.019,57.62) 63.056,57.657 63.164,57.657 63.411,57.904 69.321,57.894 70.656,59.237 U_MAIN.31
  Bottom w0.25: v1(59.393,55.849) 59.411,55.867 59.497,55.867 61.25,57.62 v1(63.019,57.62)
usb-dp-port-tie: J_USB.8 J_USB.10 U_ESD.1 | length 11.4
  Top w0.15: J_USB.8 v1(34.8,55.15) ; J_USB.10 v1(34.8,56.15)
  Top w0.25: J_USB.10 32.925,56.074 34.203,56.209 36.754,53.512 U_ESD.1
  Bottom w0.15: v1(34.8,55.15) v1(34.8,56.15)
USB_CC1: J_USB.6 R_CC1.1 | length 12
  Top w0.15: J_USB.6 32.937,54.062 33.561,54.062 34.682,52.941 34.691,52.777 34.683,49.717 33.456,48.501 33.302,48.102 33.464,45.824 R_CC1.1
USB_CC2: J_USB.12 R_CC2.1 | length 16.5
  Top w0.15: J_USB.12 33.649,57.15 33.904,56.895 34.49,56.895 v1(36.271,55.983) ; v1(37.706,47.439) 37.727,47.418 38.89,46.255 R_CC2.1
  Bottom w0.15: v1(36.271,55.983) 36.217,55.929 36.217,55.821 36.217,48.928 v1(37.706,47.439)
USB_VBUS_BOTTOM_LOCAL: J_USB.13 J_USB.14 R_USB_VBUS_BOTTOM_LINK.1 | length 1.5
  Top w0.3: J_USB.14 J_USB.14@32.849,57.8 ; J_USB.13 32.927,57.95 33.005,57.95 33.083,57.95 33.161,57.95 33.239,57.95 33.317,57.95 33.394,57.95 33.472,57.95 33.499,57.95
  Top w0.475: J_USB.13@32.849,57.8 J_USB.13 ; 33.499,57.95 R_USB_VBUS_BOTTOM_LINK.1@33.762,57.95
  Top w0.5: R_USB_VBUS_BOTTOM_LINK.1@33.762,57.95 34.025,57.95 R_USB_VBUS_BOTTOM_LINK.1
USB_VBUS_TOP_LOCAL: J_USB.3 J_USB.4 R_USB_VBUS_TOP_LINK.1 | length 6.6
  Top w0.3: J_USB.4 32.849,53 J_USB.3 32.834,52.865 32.24,52.865 32.646,52.865 33.052,52.865 33.458,52.865 33.499,52.865 ; J_USB.3@33.125,52.904 33.224,52.85 J_USB.3@33.349,52.85
  Top w0.423: J_USB.3@32.999,52.948 33.432,52.907 33.864,52.865
  Top w0.442: J_USB.3@33.349,52.85 33.4,52.9 33.499,52.889
  Top w0.5: J_USB.3@32.999,52.948 J_USB.3@33.125,52.904 ; 33.499,52.865 33.864,52.865 ; 33.499,52.889 33.849,52.85 33.958,52.85 34.25,52.591 34.227,51.042 R_USB_VBUS_TOP_LINK.1
VBUS5: C_LDO_IN.1 R_USB_VBUS_BOTTOM_LINK.2 R_USB_VBUS_TOP_LINK.2 U_ESD.5 U_LDO.1 U_LDO.3 | length 28.7
  Top w0.325: v1(37.864,62.342) 38.022,62.486 U_LDO.1@38.35,62.814
  Top w0.45: U_LDO.1@38.35,62.814 U_LDO.1
  Top w0.5: C_LDO_IN.1 36.45,63.525 U_LDO.3 ; R_USB_VBUS_TOP_LINK.2 35.9,50.9 36.15,51.15 36.4,51.15 36.65,51.4 36.9,51.4 37.15,51.65 37.4,51.65 37.65,51.9 38.15,51.9 39.15,52.9 39.15,53.65 39.9,54.4 ; v1(36.454,62.363) 36.454,62.73 36.454,63.096 U_LDO.3 ; U_LDO.3 36.101,62.766 35.752,62.433 35.404,62.099 35.275,60.4 35.725,59.95 R_USB_VBUS_BOTTOM_LINK.2 36.225,58 36.725,58 36.65,57.925 36.65,57.9 37.15,57.9 39.15,55.9 39.15,55.15 39.9,54.4 ; 39.9,54.4 U_ESD.5 39.9,54.4
  Bottom w0.5: v1(36.454,62.363) 36.475,62.342 v1(37.864,62.342)
VCC_3V3: C_3V3_BULK.1 C_LDO_OUT.1 C_MCU_BULK.1 C_MCU_VDD.1 C_MCU_VUSB.1 C_SENSOR_VDD.1 C_SENSOR_VDDIO.1 J_SENSOR_IO.1 J_SWD.1 R_I2C_SCL.2 R_I2C_SDA.2 R_MCU_RESET.2 R_SENSOR_BOOT.2 R_SENSOR_CS.2 R_SENSOR_HUB_SCL.2 R_SENSOR_HUB_SDA.2 R_SENSOR_RESET.2 U_LDO.5 U_MAIN.29 U_MAIN.40 U_SENSOR.3 U_SENSOR.28 | length 168.5
  Top w0.25: U_SENSOR.3@99.8,53.087 U_SENSOR.3 U_SENSOR.3@99.8,53.187 ; 100.6,51.4 100.65,51.589 U_SENSOR.28
  Top w0.275: 38.309,68.903 38.594,68.628 38.59,68.241 38.587,67.854
  Top w0.3: v1(69.378,59.022) 69.494,59.121 69.5,59.128 69.642,59.272 69.646,59.661 U_MAIN.29 U_MAIN.29@69.65,60.425 ; 71.668,55.202 71.939,54.938 72.21,54.673 ; U_MAIN.40@72.77,54.658 U_MAIN.40
  Top w0.312: 72.21,54.673 U_MAIN.40@72.49,54.666 ; C_MCU_BULK.1@77.962,54.426 78.199,54.188 v1(78.196,53.95)
  Top w0.319: U_SENSOR.28 100.717,51.77 100.689,51.5
  Top w0.327: U_MAIN.40@73.162,54.705 73.26,54.677 U_MAIN.40@73.583,54.683
  Top w0.337: U_MAIN.40@72.49,54.666 U_MAIN.40@72.77,54.658 ; U_MAIN.40 U_MAIN.40@73.162,54.705
  Top w0.35: 38.025,69.178 38.309,68.903 ; v1(65.58,64.219) 65.735,64.026 65.89,63.833 65.89,63.617 C_MCU_VUSB.1
  Top w0.387: 38.583,67.467 38.587,67.854 ; U_MAIN.40@73.583,54.683 73.905,54.689
  Top w0.4: C_LDO_OUT.1 37.456,69.728 37.74,69.453 38.025,69.178 ; 38.583,67.467 38.58,67.08 38.576,66.693 38.572,66.306 38.569,65.919 U_LDO.5 44.613,65.7 C_3V3_BULK.1 53.672,74.771 J_SWD.1 ; C_MCU_VUSB.1 66.109,63.181 66.327,62.963 66.546,62.744 66.932,62.744 67.319,62.744 67.706,62.744 67.983,62.467 68.261,62.189 68.539,61.911 68.817,61.633 69.094,61.356 69.6,61 U_MAIN.29@69.65,60.425 ; v1(70.313,56.524) 70.584,56.26 70.855,55.995 71.126,55.731 71.397,55.467 71.668,55.202 ; 73.905,54.689 74.228,54.694 74.55,54.7 C_MCU_VDD.1 74.89,55.88 R_MCU_RESET.2 77.488,55.323 C_MCU_BULK.1 77.725,54.663 C_MCU_BULK.1@77.962,54.426 ; v1(84.246,47.759) 84.3,47.705 84.3,47.655 84.497,47.459 84.693,47.262 84.89,47.065 84.89,46.733 R_I2C_SDA.2 84.89,46.809 84.826,46.873 84.826,46.96 v1(84.923,47.057) ; v1(87.649,73.403) 87.649,66.641 C_SENSOR_VDD.1 95.975,58.4 96.6,57.6 96.799,57.576 96.842,57.576 v1(96.979,57.439) ; v1(88,47.2) 88.09,47.2 R_I2C_SCL.2 88.89,46.711 88.89,47.023 88.8,47.113 v1(88.8,47.2) ; v1(89.62,44.82) 89.828,44.822 90.036,44.823 90.314,44.551 90.592,44.279 90.87,44.006 91.8,43.2 91.704,43.189 91.694,42.907 91.684,42.626 R_SENSOR_RESET.2 92.278,42.4 92.646,42.4 93.014,42.4 93.382,42.4 93.75,42.4 94.118,42.4 94.486,42.4 94.854,42.4 95.222,42.4 95.59,42.4 95.958,42.4 96.121,42.228 96.6,41.6 97.4,41.8 97.655,42.24 R_SENSOR_BOOT.2 ; v1(97.042,55.64) 97.042,55.255 97.042,54.869 97.316,54.595 97.59,54.321 97.864,54.047 98.139,53.773 98.8,52.8 100,53.2 U_SENSOR.3 ; v1(99.362,52.99) 99.8,53.087 ; 99.8,53.187 99.7,53.2 99.3,52.6 99.503,52.422 99.503,52.094 99.503,51.765 99.503,51.437 99.752,51.188 100,50.939 100.4,51.2 100.6,51.4 ; v1(100.645,51.088) 100.681,51.429 100.689,51.5 ; v1(100.786,56.968) 100.829,57.011 100.966,57.011 101.1,57.2 102.117,57.011 102.501,57.011 102.779,57.289 103.056,57.566 103.334,57.844 103.612,58.122 C_SENSOR_VDDIO.1 104.138,58.144 104.6,57.6 105.677,57.892 105.999,57.893 106.256,58.152 106.512,58.412 106.768,58.671 107.025,58.93 108.2,59.2 108.645,58.665 R_SENSOR_HUB_SCL.2 109.265,58.4 109.62,58.4 109.975,58.4 110.33,58.4 110.685,58.4 111.04,58.4 111.4,59 112.2,59.2 R_SENSOR_HUB_SDA.2 ; v1(101.147,47.05) 101.199,47.006 100.925,46.732 100.651,46.458 100.377,46.184 100.102,45.91 99.828,45.636 99.554,45.362 99.28,45.088 99.006,44.814 98.732,44.54 98.458,44.266 98.184,43.992 97.91,43.717 97.91,43.388 97.91,43.059 97.91,42.729 R_SENSOR_BOOT.2 ; R_SENSOR_CS.2 103.645,42.135 103.2,41.6 101.86,41.87 101.48,41.87 101.1,41.87 100.72,41.87 100.34,41.87 99.96,41.87 99.58,41.87 99.2,41.87 98.82,41.87 98.44,41.87 98.175,42.135 R_SENSOR_BOOT.2
  Bottom w0.4: J_SWD.1 65.58,73.259 65.58,72.866 65.58,72.473 65.58,72.08 65.58,71.687 65.58,71.294 65.58,70.901 65.58,70.508 65.58,70.115 65.58,69.722 65.58,69.329 65.58,68.935 65.58,68.542 65.58,68.149 65.58,67.756 65.58,67.363 65.58,66.97 65.58,66.577 65.58,66.184 65.58,65.791 65.58,65.398 65.58,65.005 65.58,64.612 v1(65.58,64.219) ; v1(69.378,59.022) 69.604,58.796 69.83,58.57 70.056,58.344 70.281,58.119 70.281,57.743 70.281,57.368 70.281,56.993 70.281,56.617 70.281,56.556 v1(70.313,56.524) ; v1(78.196,53.95) 78.201,53.952 78.475,53.677 78.75,53.402 79.025,53.127 79.3,52.852 79.575,52.578 79.849,52.303 80.124,52.028 80.399,51.753 80.674,51.478 80.949,51.204 81.223,50.929 81.498,50.654 81.773,50.379 82.048,50.105 82.322,49.83 82.597,49.555 82.872,49.28 83.147,49.005 83.422,48.731 83.696,48.456 83.971,48.181 84.246,47.906 v1(84.246,47.759) ; v1(84.923,47.057) 87.928,47.062 87.928,47.128 v1(88,47.2) ; J_SENSOR_IO.1 87.51,73.547 87.614,73.443 87.614,73.438 v1(87.649,73.403) ; v1(88.8,47.2) 88.8,46.843 88.8,46.486 88.8,46.128 88.8,45.771 89.052,45.519 89.304,45.267 89.557,45.014 89.557,44.883 v1(89.62,44.82) ; v1(96.979,57.439) 96.979,57.102 96.979,56.764 96.979,56.427 96.979,56.089 96.979,55.752 97.023,55.708 97.023,55.659 v1(97.042,55.64) ; v1(99.362,52.99) 99.45,53.118 99.45,53.151 99.5,53.2 99.45,54.215 99.45,54.569 99.45,54.923 99.45,55.278 99.45,55.632 99.717,55.899 99.9,56.6 100.519,56.701 v1(100.786,56.968) ; v1(100.645,51.088) 100.6,51 100.936,50.665 101.139,50.454 101.14,50.076 101.141,49.698 100.9,49.4 101.143,48.563 101.144,48.185 101.145,47.806 101.146,47.428 v1(101.147,47.05)
pads on no net: J_SWD.6 J_SWD.7 J_SWD.8 J_USB.5 J_USB.11 J_USB.NPTH-1 J_USB.NPTH-2 U_LDO.4 U_MAIN.1 U_MAIN.2 U_MAIN.3 U_MAIN.4 U_MAIN.5 U_MAIN.6 U_MAIN.7 U_MAIN.8 U_MAIN.9 U_MAIN.10 U_MAIN.11 U_MAIN.14 U_MAIN.15 U_MAIN.16 U_MAIN.17 U_MAIN.18 U_MAIN.19 U_MAIN.20 U_MAIN.21 U_MAIN.22 U_MAIN.23 U_MAIN.24 U_MAIN.25 U_MAIN.26 U_MAIN.27 U_MAIN.28 U_MAIN.33 U_MAIN.34 U_MAIN.35 U_MAIN.36 U_MAIN.37 U_MAIN.39 U_MAIN.43 U_MAIN.44 U_MAIN.45 U_MAIN.46 U_MAIN.49 U_MAIN.52 U_MAIN.53 U_MAIN.54 U_MAIN.55 U_MAIN.56 U_MAIN.57 U_MAIN.58 U_MAIN.59 U_MAIN.60 U_MAIN.61 U_MAIN.62 U_MAIN.63 U_MAIN.64 U_SENSOR.1 U_SENSOR.7 U_SENSOR.8 U_SENSOR.12 U_SENSOR.13 U_SENSOR.21 U_SENSOR.22 U_SENSOR.23 U_SENSOR.24
copper on no net:
  other v2: 37.2,54.4

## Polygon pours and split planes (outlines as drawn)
GND on Bottom (solid): 117.1,85.1 25.7,85.1 25.7,25.7 117.1,25.7
GND on Bottom (solid): 65.601,76.566 65.389,76.566 65.39,76.565 65.484,76.452 65.495,76.43 65.506,76.452 65.6,76.565
GND on Bottom (solid): 65.495,75.64 65.484,75.618 65.399,75.515 65.591,75.515 65.506,75.618
GND on Bottom (solid): 65.61,75.496 65.61,75.304 65.713,75.389 65.735,75.4 65.713,75.411
GND on Bottom (solid): 69.305,75.64 69.294,75.618 69.2,75.505 69.087,75.411 69.065,75.4 69.087,75.389 69.2,75.295 69.294,75.182 69.305,75.16 69.316,75.182 69.41,75.295 69.523,75.389 69.545,75.4 69.523,75.411 69.41,75.505 69.316,75.618
GND on Bottom (solid): 68.035,75.64 68.024,75.618 67.93,75.505 67.817,75.411 67.795,75.4 67.817,75.389 67.93,75.295 68.024,75.182 68.035,75.16 68.046,75.182 68.14,75.295 68.253,75.389 68.275,75.4 68.253,75.411 68.14,75.505 68.046,75.618
GND on Bottom (solid): 66.765,75.64 66.754,75.618 66.66,75.505 66.547,75.411 66.525,75.4 66.547,75.389 66.66,75.295 66.754,75.182 66.765,75.16 66.776,75.182 66.87,75.295 66.983,75.389 67.005,75.4 66.983,75.411 66.87,75.505 66.776,75.618
GND on Bottom (solid): 64.331,76.566 64.197,76.566 58.796,71.165 58.796,65.437 58.829,65.455 58.904,65.477 58.982,65.485 59.06,65.477 59.135,65.455 59.204,65.418 59.265,65.368 59.315,65.307 59.316,65.304 59.317,70.767 59.322,70.821 59.338,70.872 59.363,70.92 59.398,70.961 64.173,75.737 64.167,75.748 64.124,75.889 64.11,76.035 64.124,76.181 64.167,76.322 64.236,76.452 64.33,76.565
GND on Bottom (solid): 59.316,64.866 59.315,64.863 59.265,64.802 59.257,64.796 59.257,63.948 59.264,63.943 59.314,63.882 59.316,63.878
GND on Bottom (solid): 59.316,63.442 59.314,63.438 59.264,63.377 59.203,63.327 59.134,63.29 59.059,63.268 58.981,63.26 58.903,63.268 58.828,63.29 58.796,63.307 58.796,58.269 59.05,58.015 59.06,58.016 59.138,58.008 59.213,57.986 59.282,57.949 59.315,57.921
GND on Bottom (solid): 100.339,57.087 100.051,57.087 99.982,57.019 100.327,57.075
GND on Bottom (solid): 105.142,60.071 105.109,60.03 105.101,60.024 105.101,53.745 105.416,53.43 105.418,53.438 105.455,53.507 105.505,53.567 105.565,53.617 105.617,53.645 105.223,54.04 105.188,54.081 105.163,54.129 105.147,54.18 105.142,54.234

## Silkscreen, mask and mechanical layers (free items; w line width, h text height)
Top Overlay:
  text "3V3 • SWD • 2L" at 43.4,83.4 h0.48
  text "I2C 0x4A • USB-C FS" at 98.4,83.4 h0.5
  text "MSPM0G5187SPMR • NATIVE USB" at 60.4,29.9 h0.52
  text "BNO085" at 101.4,29.9 h0.55
  text "QUICK CONFIGURE • SENSOR BOARD" at 76.4,27.4 h0.65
